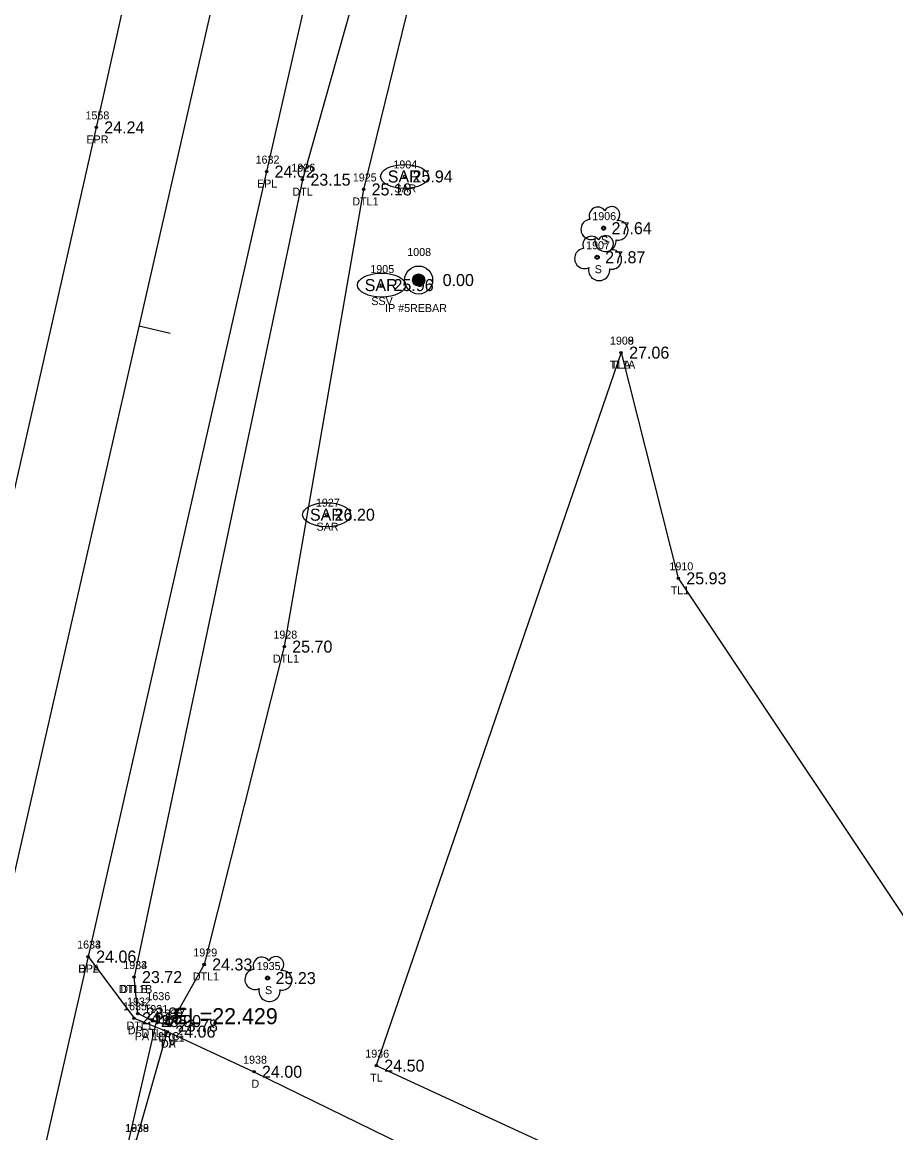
# Model space of a CAD drawing. Extents: x 2654414 to 2656963, y 761776 to 764965.
# Drawn here: x 2655574.4 to 2655683.5, y 762588.5 to 762727.3 of the extents above; entities that cross this region are included whole.
import ezdxf

# ---------------------------------------------------------------- set-up
doc = ezdxf.new("R2010")
doc.units = 0
for name, color, linetype in [('Default', 7, 'Continuous'), ('RD_EX_DR_Pipe', 7, 'Continuous'), ('RD_EX_DR_Pipe_txCode', 7, 'Continuous'), ('RD_EX_Driveway', 7, 'Continuous'), ('RD_EX_Driveway_txCode', 7, 'Continuous'), ('RD_EX_DV_Prop_txCode', 7, 'Continuous'), ('RD_EX_DV_PropPin', 7, 'Continuous'), ('RD_EX_H2O', 7, 'Continuous'), ('RD_EX_H2O_txCode', 7, 'Continuous'), ('RD_EX_Road', 7, 'Continuous'), ('RD_EX_Road_txCode', 7, 'Continuous'), ('RD_EX_SU_Sewer', 7, 'Continuous'), ('RD_EX_TX_Driveway_ELEV', 7, 'Continuous'), ('RD_EX_TX_DV_Prop_ELEV', 7, 'Continuous'), ('RD_EX_TX_H2O_ELEV', 7, 'Continuous'), ('RD_EX_TX_Road_ELEV', 7, 'Continuous'), ('RD_EX_TX_UT_ELEV', 7, 'Continuous'), ('RD_EX_TX_VEG_ELEV', 7, 'Continuous'), ('RD_EX_UT', 7, 'Continuous'), ('RD_EX_UT_txCode', 7, 'Continuous'), ('RD_EX_VEG', 7, 'Continuous'), ('RD_EX_VEG_txCode', 7, 'Continuous'), ('RD_HC_Cl', 7, 'Continuous'), ('RD_HC_Data_Tic', 7, 'Continuous'), ('RD_SMD_Locator', 7, 'Continuous'), ('RD_TX_Pipe_ElevEX', 7, 'Continuous')]:
    doc.layers.add(name, color=color, linetype=linetype)

msp = doc.modelspace()

# ---------------------------------------------------------------- linework, layer by layer
at = {"layer": 'Default'}
msp.add_line((2656050.51, 764712.37), (2655383.26, 761787.51), dxfattribs=at)
at = {"layer": 'RD_EX_DR_Pipe'}
msp.add_line((2655591.31, 762603.09), (2655583.89, 762571.36), dxfattribs=at)
at = {"layer": 'RD_EX_Driveway'}
for points in [[(2655582.64, 762610.54), (2655588.38, 762602.83), (2655592.52, 762601.16), (2655588.62, 762587.62), (2655581.94, 762586.42), (2655576.46, 762583.32)], [(2655592.52, 762601.16), (2655603.35, 762596.15), (2655666.52, 762565.25)]]:
    msp.add_lwpolyline(points, dxfattribs=at)
at = {"layer": 'RD_EX_DV_PropPin'}
for p, q in [((2655623.19, 762694.87), (2655623.19, 762695.27)), ((2655623.22, 762694.77), (2655623.22, 762695.37)), ((2655623.26, 762694.7), (2655623.26, 762695.44)), ((2655623.29, 762694.64), (2655623.29, 762695.5)), ((2655623.33, 762694.6), (2655623.33, 762695.54)), ((2655623.36, 762694.56), (2655623.36, 762695.59)), ((2655623.4, 762694.52), (2655623.4, 762695.62)), ((2655623.43, 762694.49), (2655623.43, 762695.65)), ((2655623.47, 762694.46), (2655623.47, 762695.68)), ((2655623.5, 762694.44), (2655623.5, 762695.71)), ((2655623.54, 762694.41), (2655623.54, 762695.73)), ((2655623.57, 762694.39), (2655623.57, 762695.75)), ((2655623.61, 762694.38), (2655623.61, 762695.76)), ((2655623.64, 762694.36), (2655623.64, 762695.78)), ((2655623.68, 762694.35), (2655623.68, 762695.79)), ((2655623.71, 762694.34), (2655623.71, 762695.8)), ((2655623.75, 762694.33), (2655623.75, 762695.81)), ((2655623.78, 762694.32), (2655623.78, 762695.82)), ((2655623.82, 762694.32), (2655623.82, 762695.82)), ((2655623.85, 762694.31), (2655623.85, 762695.83)), ((2655623.89, 762694.31), (2655623.89, 762695.83)), ((2655623.92, 762694.31), (2655623.92, 762695.83)), ((2655623.96, 762694.31), (2655623.96, 762695.83)), ((2655623.99, 762694.31), (2655623.99, 762695.83)), ((2655624.03, 762694.32), (2655624.03, 762695.82)), ((2655624.06, 762694.32), (2655624.06, 762695.82)), ((2655624.1, 762694.33), (2655624.1, 762695.81)), ((2655624.13, 762694.34), (2655624.13, 762695.8)), ((2655624.17, 762694.35), (2655624.17, 762695.79)), ((2655624.2, 762694.36), (2655624.2, 762695.78)), ((2655624.24, 762694.38), (2655624.24, 762695.76)), ((2655624.27, 762694.39), (2655624.27, 762695.75)), ((2655624.31, 762694.41), (2655624.31, 762695.73)), ((2655624.34, 762694.44), (2655624.34, 762695.71)), ((2655624.38, 762694.46), (2655624.38, 762695.68)), ((2655624.41, 762694.49), (2655624.41, 762695.65)), ((2655624.45, 762694.52), (2655624.45, 762695.62)), ((2655624.48, 762694.56), (2655624.48, 762695.59)), ((2655624.52, 762694.6), (2655624.52, 762695.54)), ((2655624.55, 762694.64), (2655624.55, 762695.5)), ((2655624.59, 762694.7), (2655624.59, 762695.44)), ((2655624.62, 762694.77), (2655624.62, 762695.37)), ((2655624.66, 762694.87), (2655624.66, 762695.27))]:
    msp.add_line(p, q, dxfattribs=at)
for radius in [1.75, 0.761]:
    msp.add_circle((2655623.92, 762695.07), radius, dxfattribs=at)
at = {"layer": 'RD_EX_H2O'}
for points in [[(2655616.83, 762733.96), (2655623.42, 762732.41), (2655617.05, 762706.39), (2655607.13, 762649.27), (2655597.13, 762609.55), (2655592.83, 762601.92), (2655590.72, 762602.48), (2655588.85, 762603.42), (2655588.37, 762607.98)], [(2655616.83, 762733.96), (2655609.4, 762707.61), (2655588.37, 762607.98)]]:
    msp.add_lwpolyline(points, dxfattribs=at)
at = {"layer": 'RD_EX_Road'}
for points in [[(2655700.99, 763232.28), (2655693.55, 763198.57), (2655671.65, 763102.04), (2655649.04, 763001.06), (2655627.27, 762906.23), (2655605, 762809.37), (2655598.99, 762783.09), (2655583.65, 762714.14), (2655561.97, 762618.32), (2655556.36, 762593.84), (2655548.11, 762557.14), (2655540.1, 762522.48), (2655518.03, 762425.04), (2655496.48, 762329.56), (2655475.55, 762236.62), (2655473.2, 762226.14), (2655466.57, 762197.5), (2655460.06, 762168.16), (2655454.26, 762143.78), (2655432.5, 762049.88), (2655410.7, 761955.51), (2655388.17, 761858.43), (2655373.5, 761793.95)], [(2655670.04, 762995.18), (2655648.57, 762900.67), (2655631.27, 762824.03), (2655626.67, 762802.87), (2655621.78, 762781.91), (2655611.71, 762738.43), (2655604.93, 762708.62), (2655582.64, 762610.54), (2655576.46, 762583.32), (2655561.41, 762517.24), (2655539.15, 762414.81), (2655531.98, 762386.15), (2655517.98, 762324.29), (2655508.17, 762280.15), (2655501.46, 762251.6), (2655496.92, 762232.09), (2655477.2, 762144.97), (2655472.14, 762122.52), (2655453.74, 762045.1), (2655431.79, 761949.92), (2655409.76, 761853.25), (2655401.25, 761816.42), (2655394.61, 761787.37)]]:
    msp.add_lwpolyline(points, dxfattribs=at)
at = {"layer": 'RD_EX_SU_Sewer'}
for centre in [(2655622.16, 762708.01), (2655612.43, 762665.75)]:
    msp.add_ellipse(centre, major_axis=(-3, 0), ratio=0.5, dxfattribs=at)
at = {"layer": 'RD_EX_UT'}
msp.add_circle((2655619.28, 762694.44), 0.15, dxfattribs=at)
msp.add_ellipse((2655619.28, 762694.44), major_axis=(-3, 0), ratio=0.5, dxfattribs=at)
at = {"layer": 'RD_EX_VEG'}
for points in [[(2655649.21, 762686), (2655618.63, 762596.91), (2655674.05, 762571.37)], [(2655649.21, 762686), (2655656.35, 762657.8), (2655689.45, 762608.19)]]:
    msp.add_lwpolyline(points, dxfattribs=at)
for centre in [(2655647.02, 762701.55), (2655646.22, 762697.92), (2655605.05, 762607.85)]:
    msp.add_circle(centre, 0.25, dxfattribs=at)
for centre, radius, start, end in [((2655646.3, 762703.1), 1.08, 34.9763, 204.756), ((2655648.06, 762703.25), 0.995, 308.7626, 152.0467), ((2655645.45, 762701.4), 1.26, 96.4518, 294.734), ((2655648.86, 762701.27), 1.22, 256.5667, 98.1046), ((2655645.5, 762699.46), 1.08, 34.9763, 204.756), ((2655647.26, 762699.95), 1.32, 166.8827, 5.7589), ((2655647.27, 762699.62), 0.995, 308.7626, 152.0467), ((2655644.66, 762697.76), 1.26, 96.4518, 294.734), ((2655648.06, 762697.64), 1.22, 256.5667, 98.1046), ((2655646.47, 762696.32), 1.32, 166.8827, 5.7589), ((2655604.33, 762609.39), 1.08, 34.9763, 204.756), ((2655606.09, 762609.55), 0.995, 308.7626, 152.0467), ((2655603.48, 762607.69), 1.26, 96.4518, 294.734), ((2655606.89, 762607.57), 1.22, 256.5667, 98.1046), ((2655605.29, 762606.25), 1.32, 166.8827, 5.7589)]:
    msp.add_arc(centre, radius, start, end, dxfattribs=at)
at = {"layer": 'RD_HC_Cl'}
msp.add_line((2656050.51, 764712.37), (2655383.26, 761787.51), dxfattribs=at)
at = {"layer": 'RD_HC_Data_Tic'}
msp.add_line((2655589, 762689.34), (2655592.9, 762688.45), dxfattribs=at)
at = {"layer": 'RD_SMD_Locator'}
for centre, radius in [((2655583.65, 762714.14), 0.15), ((2655604.93, 762708.62), 0.15), ((2655609.4, 762707.61), 0.15), ((2655622.16, 762708.01), 0.15), ((2655617.05, 762706.39), 0.15), ((2655647.02, 762701.55), 0.15), ((2655646.22, 762697.92), 0.15), ((2655623.92, 762695.07), 0.15), ((2655649.21, 762686), 0.15), ((2655649.21, 762686), 0.15), ((2655612.43, 762665.75), 0.15), ((2655656.35, 762657.8), 0.15), ((2655607.13, 762649.27), 0.15), ((2655582.64, 762610.54), 0.15), ((2655582.64, 762610.54), 0.15), ((2655597.13, 762609.55), 0.15), ((2655588.37, 762607.98), 0.15), ((2655588.37, 762607.98), 0.15), ((2655605.05, 762607.85), 0.15), ((2655588.85, 762603.42), 0.15), ((2655588.38, 762602.83), 0.15), ((2655590.72, 762602.48), 0.15), ((2655591.31, 762603.09), 0.2), ((2655592.52, 762601.16), 0.15), ((2655592.52, 762601.16), 0.15), ((2655592.83, 762601.92), 0.15), ((2655618.63, 762596.91), 0.15), ((2655603.35, 762596.15), 0.15)]:
    msp.add_circle(centre, radius, dxfattribs=at)

# ---------------------------------------------------------------- texts
at = {"layer": 'RD_EX_DR_Pipe_txCode'}
for s, p in [('1636', (2655589.92, 762605.09)), ('PA 18RC', (2655588.47, 762600.09))]:
    msp.add_text(s, height=1, dxfattribs=at).set_placement(p)
at = {"layer": 'RD_EX_Driveway_txCode'}
for s, p in [('1634', (2655581.27, 762611.54)), ('DPA', (2655581.38, 762608.54)), ('1635', (2655587.01, 762603.83)), ('1637', (2655591.15, 762602.16)), ('1937', (2655591.17, 762602.16)), ('DP', (2655587.6, 762600.83)), ('DA', (2655591.72, 762599.16)), ('DP', (2655591.74, 762599.16)), ('1938', (2655602, 762597.15)), ('D', (2655603.04, 762594.15)), ('1638', (2655587.25, 762588.62)), ('1939', (2655587.27, 762588.62))]:
    msp.add_text(s, height=1, dxfattribs=at).set_placement(p)
at = {"layer": 'RD_EX_DV_Prop_txCode'}
for s, p in [('1008', (2655622.5, 762698.07)), ('IP #5REBAR', (2655619.73, 762691.07))]:
    msp.add_text(s, height=1, dxfattribs=at).set_placement(p)
at = {"layer": 'RD_EX_H2O_txCode'}
for s, p in [('1926', (2655608.03, 762708.61)), ('1925', (2655615.7, 762707.39)), ('DTL', (2655608.16, 762705.61)), ('DTL1', (2655615.64, 762704.39)), ('1928', (2655605.78, 762650.27)), ('DTL1', (2655605.72, 762647.27)), ('1929', (2655595.78, 762610.55)), ('1933', (2655587.03, 762608.98)), ('1934', (2655587.03, 762608.98)), ('DTL1', (2655595.72, 762607.55)), ('DTL1B', (2655586.49, 762605.98)), ('DTLB', (2655586.66, 762605.98)), ('1932', (2655587.5, 762604.42)), ('1931', (2655589.66, 762603.48)), ('1930', (2655591.44, 762602.92)), ('DTL1', (2655587.44, 762601.42)), ('DTL1', (2655589.31, 762600.48)), ('DTL1', (2655591.42, 762599.92))]:
    msp.add_text(s, height=1, dxfattribs=at).set_placement(p)
at = {"layer": 'RD_EX_Road_txCode'}
for s, p in [('1558', (2655582.31, 762715.14)), ('EPR', (2655582.43, 762712.14)), ('1632', (2655603.56, 762709.62)), ('EPL', (2655603.73, 762706.62)), ('1633', (2655581.27, 762611.54)), ('EPL', (2655581.44, 762608.54))]:
    msp.add_text(s, height=1, dxfattribs=at).set_placement(p)
at = {"layer": 'RD_EX_SU_Sewer'}
for p in [(2655620.06, 762707.26), (2655610.34, 762665)]:
    msp.add_text('SAR', height=1.5, dxfattribs=at).set_placement(p)
at = {"layer": 'RD_EX_TX_Driveway_ELEV'}
for s, p in [('24.06', (2655583.64, 762609.79)), ('24.15', (2655589.38, 762602.08)), ('24.06', (2655593.52, 762600.41)), ('24.06', (2655593.52, 762600.41)), ('24.00', (2655604.35, 762595.4))]:
    msp.add_text(s, height=1.5, dxfattribs=at).set_placement(p)
at = {"layer": 'RD_EX_TX_DV_Prop_ELEV'}
msp.add_text('0.00', height=1.5, dxfattribs=at).set_placement((2655626.92, 762694.32))
at = {"layer": 'RD_EX_TX_H2O_ELEV'}
for s, p in [('23.15', (2655610.4, 762706.86)), ('25.18', (2655618.05, 762705.64)), ('25.70', (2655608.13, 762648.52)), ('24.33', (2655598.13, 762608.8)), ('23.72', (2655589.37, 762607.23)), ('23.72', (2655589.37, 762607.23)), ('23.87', (2655589.85, 762602.67)), ('23.90', (2655591.72, 762601.73)), ('23.78', (2655593.83, 762601.17))]:
    msp.add_text(s, height=1.5, dxfattribs=at).set_placement(p)
at = {"layer": 'RD_EX_TX_Road_ELEV'}
for s, p in [('24.24', (2655584.65, 762713.39)), ('24.02', (2655605.93, 762707.87)), ('24.06', (2655583.64, 762609.79))]:
    msp.add_text(s, height=1.5, dxfattribs=at).set_placement(p)
at = {"layer": 'RD_EX_TX_UT_ELEV'}
for s, p in [('25.94', (2655623.16, 762707.26)), ('25.96', (2655620.78, 762693.69)), ('26.20', (2655613.43, 762665))]:
    msp.add_text(s, height=1.5, dxfattribs=at).set_placement(p)
at = {"layer": 'RD_EX_TX_VEG_ELEV'}
for s, p in [('27.64', (2655648.02, 762700.8)), ('27.87', (2655647.22, 762697.17)), ('27.06', (2655650.21, 762685.25)), ('27.06', (2655650.21, 762685.25)), ('25.93', (2655657.35, 762657.05)), ('25.23', (2655606.05, 762607.1)), ('24.50', (2655619.63, 762596.16))]:
    msp.add_text(s, height=1.5, dxfattribs=at).set_placement(p)
at = {"layer": 'RD_EX_UT'}
msp.add_text('SAR', height=1.5, dxfattribs=at).set_placement((2655617.18, 762693.69))
at = {"layer": 'RD_EX_UT_txCode'}
for s, p in [('1904', (2655620.77, 762709.01)), ('SAR', (2655620.89, 762706.01)), ('1905', (2655617.89, 762695.94)), ('SSV', (2655618.01, 762691.94)), ('1927', (2655611.09, 762666.75)), ('SAR', (2655611.17, 762663.75))]:
    msp.add_text(s, height=1, dxfattribs=at).set_placement(p)
at = {"layer": 'RD_EX_VEG_txCode'}
for s, p in [('1906', (2655645.61, 762702.55)), ('1907', (2655644.84, 762698.92)), ('S', (2655646.71, 762699.55)), ('S', (2655645.91, 762695.92)), ('1908', (2655647.82, 762687)), ('1909', (2655647.82, 762687)), ('TL1A', (2655647.78, 762684)), ('TLA', (2655647.95, 762684)), ('1910', (2655655.25, 762658.8)), ('TL1', (2655655.41, 762655.8)), ('1935', (2655603.7, 762608.85)), ('S', (2655604.74, 762605.85)), ('1936', (2655617.26, 762597.91)), ('TL', (2655617.86, 762594.91))]:
    msp.add_text(s, height=1, dxfattribs=at).set_placement(p)
at = {"layer": 'RD_TX_Pipe_ElevEX'}
msp.add_text('EL=22.429', height=2, dxfattribs=at).set_placement((2655593.31, 762602.09))

doc.saveas('drawing.dxf')
